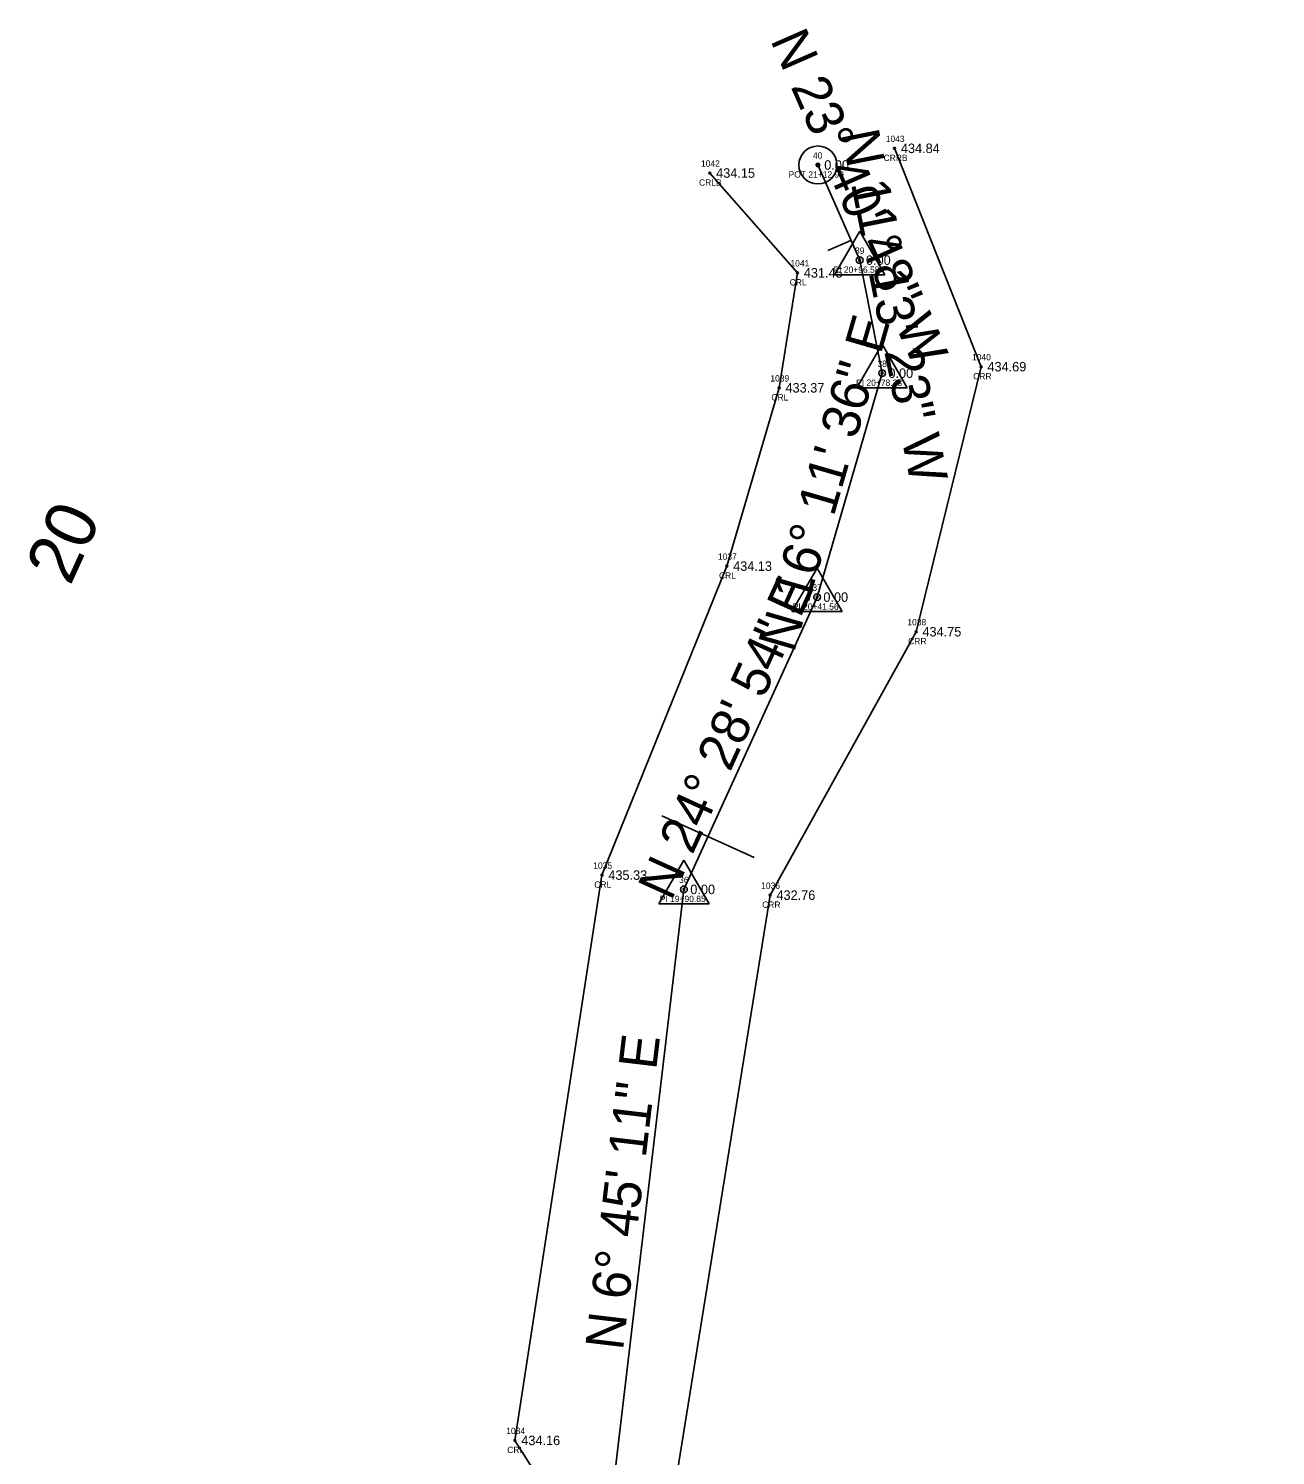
# Model space of a CAD drawing. Extents: x 1809463 to 1812121, y 790645 to 791946.
# Drawn here: x 1810635.7 to 1810832.5, y 791602.9 to 791828.2 of the extents above; entities that cross this region are included whole.
import ezdxf

# ---------------------------------------------------------------- set-up
doc = ezdxf.new("R2010")
doc.units = 0
for name, color, linetype in [('RD_EX_H2O', 7, 'Continuous'), ('RD_EX_H2O_txCode', 7, 'Continuous'), ('RD_EX_TX_H2O_ELEV', 7, 'Continuous'), ('RD_HC_Cl', 7, 'Continuous'), ('RD_HC_Data', 7, 'Continuous'), ('RD_HC_Data_Tic', 7, 'Continuous'), ('RD_HC_Survey_ELEV', 7, 'Continuous'), ('RD_HC_TX_Sta50', 7, 'Continuous'), ('RD_HC_txCode', 7, 'Continuous'), ('RD_SMD_Locator', 7, 'Continuous')]:
    doc.layers.add(name, color=color, linetype=linetype)

msp = doc.modelspace()

# ---------------------------------------------------------------- linework, layer by layer
at = {"layer": 'RD_EX_H2O'}
for points in [[(1810797.71, 791296.87), (1810832.51, 791426.19), (1810824.93, 791438.48), (1810774.65, 791454.91), (1810754.82, 791471.31), (1810756.82, 791503.13), (1810738.07, 791600.2), (1810752.73, 791691.4), (1810775.78, 791733), (1810786.04, 791774.85), (1810772.38, 791809.33)], [(1810781.61, 791303.43), (1810807.2, 791415.78), (1810808.22, 791420.49), (1810765.69, 791434.41), (1810731.68, 791459.26), (1810725.69, 791486.37), (1810718.09, 791596.36), (1810712.45, 791605.3), (1810726.19, 791694.57), (1810745.89, 791743.36), (1810754.16, 791771.51), (1810757.05, 791789.67), (1810743.21, 791805.43)]]:
    msp.add_lwpolyline(points, dxfattribs=at)
at = {"layer": 'RD_HC_Cl'}
for p, q in [((1810766.87, 791791.67), (1810760.28, 791806.7)), ((1810770.41, 791773.82), (1810766.87, 791791.67)), ((1810760.14, 791738.46), (1810770.41, 791773.82)), ((1810739.13, 791692.31), (1810760.14, 791738.46)), ((1810727.89, 791597.45), (1810739.13, 791692.31))]:
    msp.add_line(p, q, dxfattribs=at)
at = {"layer": 'RD_HC_Data'}
for p, q in [((1810762.9, 791789.38), (1810766.87, 791796.25)), ((1810766.87, 791796.25), (1810770.84, 791789.38)), ((1810762.9, 791789.38), (1810770.84, 791789.38)), ((1810766.44, 791771.53), (1810770.41, 791778.41)), ((1810770.41, 791778.41), (1810774.38, 791771.53)), ((1810766.44, 791771.53), (1810774.38, 791771.53)), ((1810756.17, 791736.17), (1810760.14, 791743.05)), ((1810760.14, 791743.05), (1810764.11, 791736.17)), ((1810756.17, 791736.17), (1810764.11, 791736.17)), ((1810735.15, 791690.02), (1810739.13, 791696.9)), ((1810739.13, 791696.9), (1810743.1, 791690.02)), ((1810735.15, 791690.02), (1810743.1, 791690.02))]:
    msp.add_line(p, q, dxfattribs=at)
for centre, radius in [((1810760.28, 791806.7), 3), ((1810760.28, 791806.7), 0.282), ((1810766.87, 791791.67), 0.529), ((1810770.41, 791773.82), 0.529), ((1810760.14, 791738.46), 0.529), ((1810739.13, 791692.31), 0.529)]:
    msp.add_circle(centre, radius, dxfattribs=at)
at = {"layer": 'RD_HC_Data_Tic'}
for p, q in [((1810765.49, 791794.8), (1810761.83, 791793.2)), ((1810742.92, 791700.64), (1810735.64, 791703.95)), ((1810742.92, 791700.64), (1810750.2, 791697.32))]:
    msp.add_line(p, q, dxfattribs=at)
at = {"layer": 'RD_SMD_Locator'}
for centre in [(1810772.38, 791809.33), (1810743.21, 791805.43), (1810760.28, 791806.7), (1810766.87, 791791.67), (1810757.05, 791789.67), (1810770.41, 791773.82), (1810786.04, 791774.85), (1810754.16, 791771.51), (1810745.89, 791743.36), (1810760.14, 791738.46), (1810775.78, 791733), (1810726.19, 791694.57), (1810739.13, 791692.31), (1810752.73, 791691.4), (1810712.45, 791605.3)]:
    msp.add_circle(centre, 0.15, dxfattribs=at)

# ---------------------------------------------------------------- texts
at = {"layer": 'RD_EX_H2O_txCode'}
for s, p in [('1043', (1810770.99, 791810.33)), ('1042', (1810741.82, 791806.43)), ('CRRB', (1810770.65, 791807.33)), ('CRLB', (1810741.51, 791803.43)), ('1041', (1810755.94, 791790.67)), ('CRL', (1810755.82, 791787.67)), ('1040', (1810784.61, 791775.85)), ('1039', (1810752.77, 791772.51)), ('CRR', (1810784.79, 791772.85)), ('CRL', (1810752.93, 791769.51)), ('1037', (1810744.5, 791744.36)), ('CRL', (1810744.66, 791741.36)), ('1038', (1810774.4, 791734)), ('CRR', (1810774.53, 791731)), ('1035', (1810724.81, 791695.57)), ('CRL', (1810724.97, 791692.57)), ('1036', (1810751.32, 791692.4)), ('CRR', (1810751.48, 791689.4)), ('1034', (1810711.07, 791606.3)), ('CRL', (1810711.23, 791603.3))]:
    msp.add_text(s, height=1, dxfattribs=at).set_placement(p)
at = {"layer": 'RD_EX_TX_H2O_ELEV'}
for s, p in [('434.84', (1810773.38, 791808.58)), ('434.15', (1810744.21, 791804.68)), ('431.45', (1810758.05, 791788.92)), ('434.69', (1810787.04, 791774.1)), ('433.37', (1810755.16, 791770.76)), ('434.13', (1810746.89, 791742.61)), ('434.75', (1810776.78, 791732.25)), ('435.33', (1810727.19, 791693.82)), ('432.76', (1810753.73, 791690.65)), ('434.16', (1810713.45, 791604.55))]:
    msp.add_text(s, height=1.5, dxfattribs=at).set_placement(p)
at = {"layer": 'RD_HC_Data'}
for s, rotation, p in [('N 23%%d 40\' 48" W', 293.68, (1810752.71, 791826.44)), ('N 11%%d 13\' 23" W', 281.223, (1810763.91, 791811.7)), ('N 16%%d 11\' 36" E', 73.8067, (1810756.51, 791729.55)), ('N 24%%d 28\' 54" E', 65.5183, (1810737.13, 791690.34)), ('N 6%%d 45\' 11" E', 83.2468, (1810729.49, 791619.4))]:
    msp.add_text(s, height=6, rotation=rotation, dxfattribs=at).set_placement(p)
at = {"layer": 'RD_HC_Survey_ELEV'}
for p in [(1810761.28, 791805.95), (1810767.87, 791790.92), (1810771.41, 791773.07), (1810761.14, 791737.71), (1810740.13, 791691.56)]:
    msp.add_text('0.00', height=1.5, dxfattribs=at).set_placement(p)
at = {"layer": 'RD_HC_TX_Sta50'}
msp.add_text('20', height=8, rotation=65.5183, dxfattribs=at).set_placement((1810642.23, 791740.12))
at = {"layer": 'RD_HC_txCode'}
for s, p in [('40', (1810759.5, 791807.7)), ('POT 21+12.99', (1810755.65, 791804.7)), ('39', (1810766.14, 791792.67)), ('PI 20+96.58', (1810762.74, 791789.67)), ('38', (1810769.68, 791774.82)), ('PI 20+78.38', (1810766.31, 791771.82)), ('37', (1810759.41, 791739.46)), ('PI 20+41.56', (1810756.3, 791736.46)), ('36', (1810738.37, 791693.31)), ('PI 19+90.85', (1810735.31, 791690.31))]:
    msp.add_text(s, height=1, dxfattribs=at).set_placement(p)

doc.saveas('drawing.dxf')
